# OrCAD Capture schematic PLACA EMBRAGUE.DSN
size A
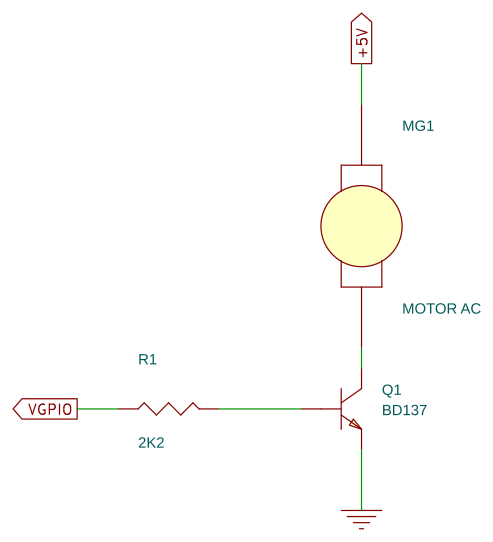
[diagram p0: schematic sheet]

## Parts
MG1  MOTOR AC
Q1  BD137
R1  2K2

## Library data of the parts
MG1 = MOTOR_AC
Q1 = BC107
R1 = R

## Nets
+5V: MG1.1
GND: Q1.1(EMITTER)
VGPIO: R1.1
N00120: MG1.2 Q1.3(COLLECTOR)
N00128: Q1.2(BASE) R1.2
